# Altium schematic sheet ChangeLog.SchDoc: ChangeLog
size A4; DocumentNumber: 7; SheetNumber: 7; SheetTotal: 8
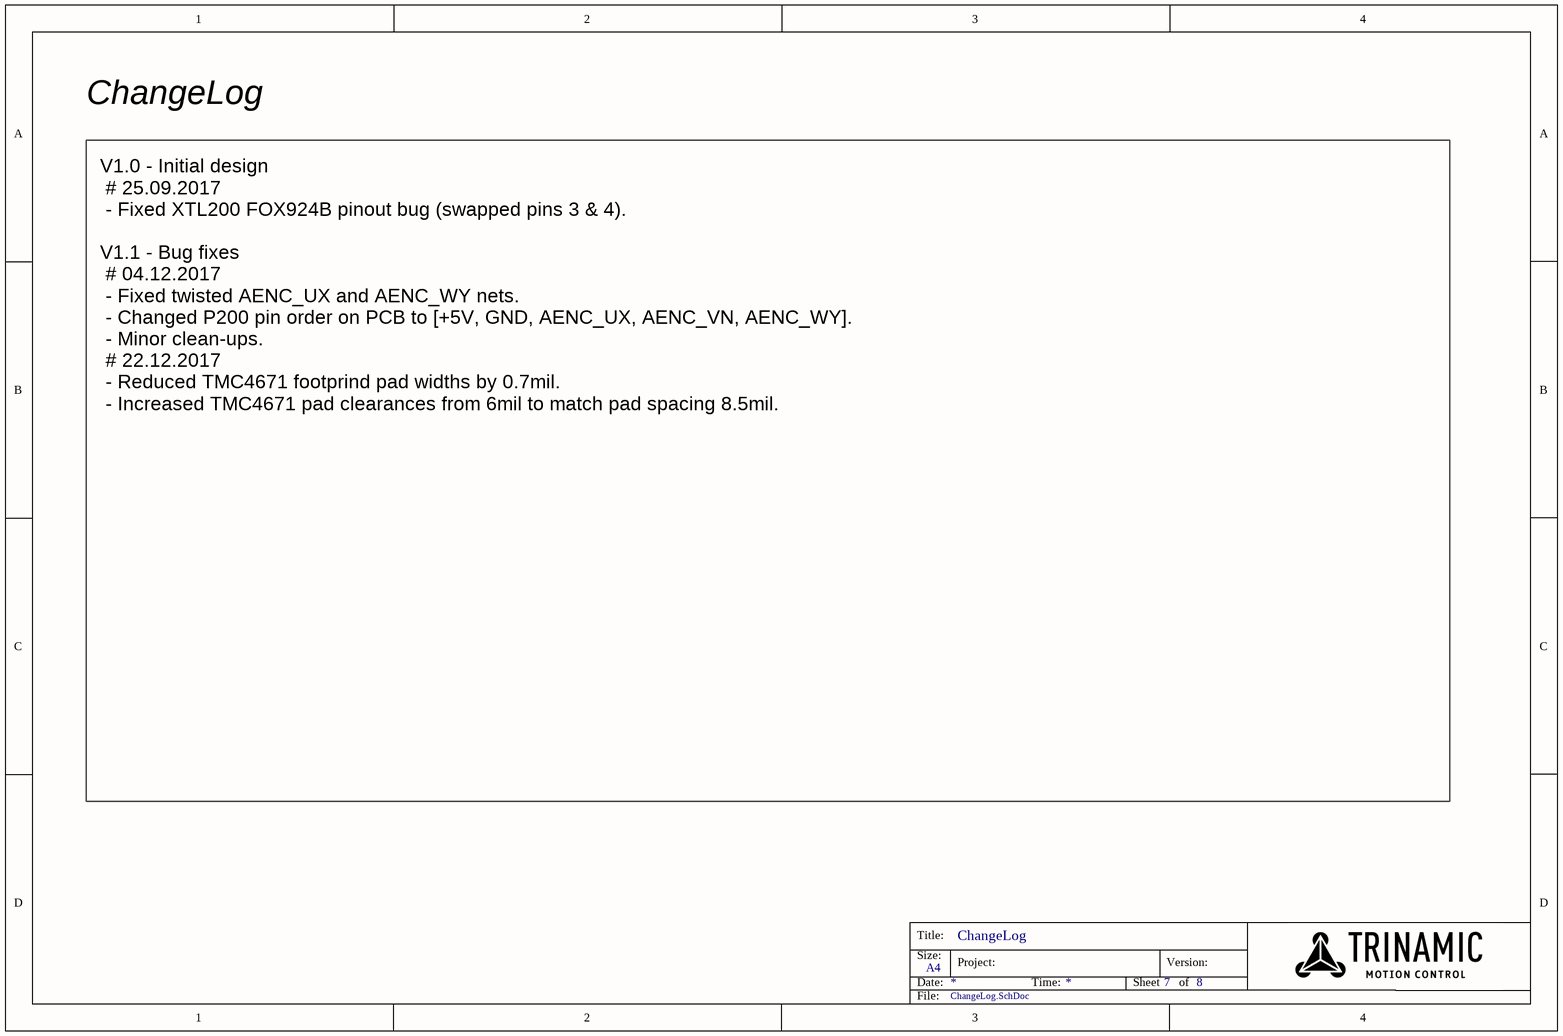
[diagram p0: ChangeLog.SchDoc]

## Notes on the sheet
- ChangeLog
- V1.0 - Initial design
  # 25.09.2017
  - Fixed XTL200 FOX924B pinout bug (swapped pins 3 & 4).
  V1.1 - Bug fixes
  # 04.12.2017
  - Fixed twisted AENC_UX and AENC_WY nets.
  - Changed P200 pin order on PCB to [+5V, GND, AENC_UX, AENC_VN, AENC_WY].
  - Minor clean-ups.
  # 22.12.2017
  - Reduced TMC4671 footprind pad widths by 0.7mil.
  - Increased TMC4671 pad clearances from 6mil to match pad spacing 8.5mil.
